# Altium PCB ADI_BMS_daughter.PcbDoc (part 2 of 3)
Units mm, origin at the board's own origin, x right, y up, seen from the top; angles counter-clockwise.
Board outline 140 x 50 mm, 4 copper layers (Top Layer, Layer 1, Layer 2, Bottom Layer), stack 1.586 mm thick; 306 components, 232 nets, 866 pads, 333 vias.
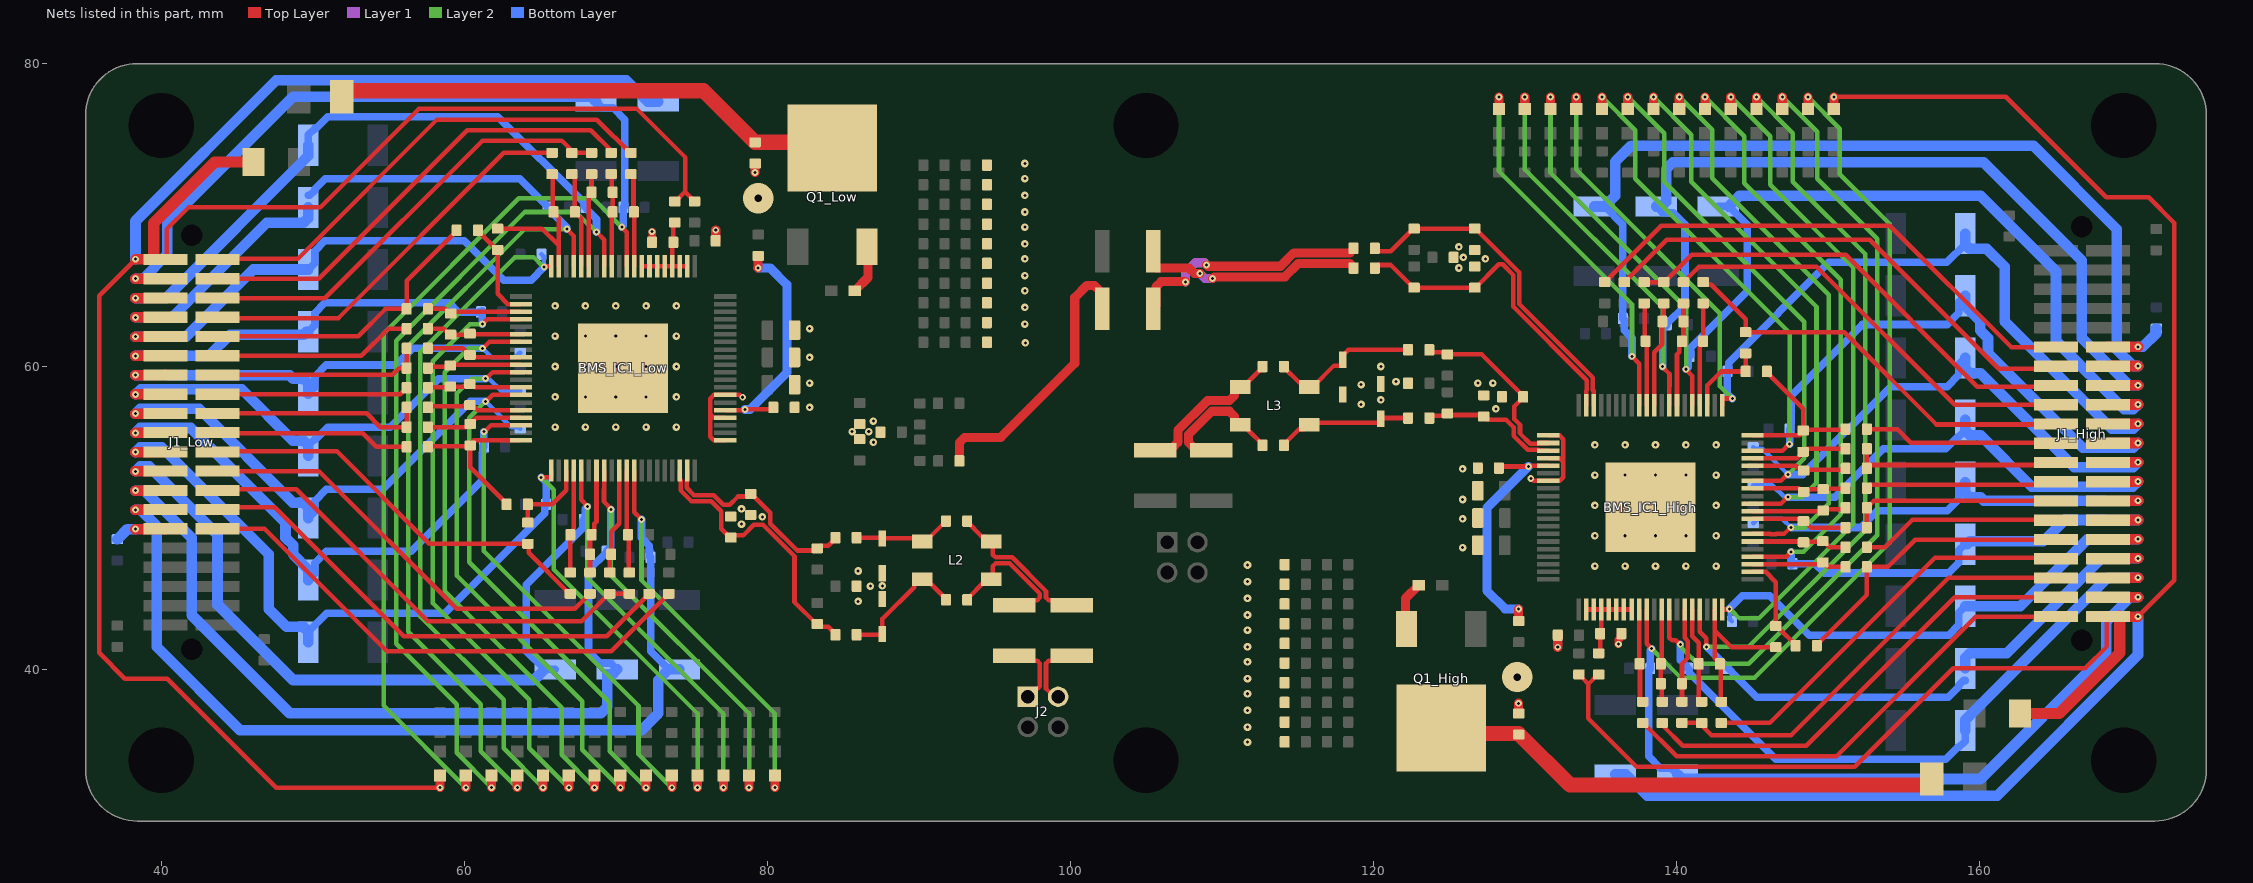
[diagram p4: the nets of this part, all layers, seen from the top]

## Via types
v1: diameter 0.45, hole 0.2, Top Layer to Bottom Layer, tented both sides, 226 vias
v2: diameter 0.5, hole 0.2, Top Layer to Bottom Layer, tented both sides, 105 vias
v3: diameter 2, hole 0.5, Top Layer to Bottom Layer, tented both sides, 2 vias

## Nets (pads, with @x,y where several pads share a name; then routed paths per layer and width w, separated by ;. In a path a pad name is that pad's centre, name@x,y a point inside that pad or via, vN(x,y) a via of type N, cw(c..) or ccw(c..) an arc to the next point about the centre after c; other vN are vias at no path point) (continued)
C2_High: BMS_IC1_High.51 C12_High.2 R15_High.2 | length 6.7
  Top Layer w0.3: R15_High.2@137.879,64.171 137.929,64.121 137.929,61.721 C12_High.2@137.979,61.671 ; BMS_IC1_High.51@138.05,57.438 C12_High.2@138.05,61.576
C2_Low: BMS_IC1_Low.51 C12_Low.2 R15_Low.2 | length 6.7
  Top Layer w0.3: C12_Low.2@70.729,48.995 BMS_IC1_Low.51@70.729,53.133 ; C12_Low.2@70.8,48.9 70.85,48.85 70.85,46.45 R15_Low.2@70.9,46.4
C3_High: BMS_IC1_High.50 C13_High.1 R16_High.2 | length 7
  Top Layer w0.3: BMS_IC1_High.50@138.55,57.438 138.55,60.943 139.079,61.471 C13_High.1@139.079,62.971 139.179,63.071 R16_High.2@139.179,64.171
C3_Low: BMS_IC1_Low.50 C13_Low.1 R16_Low.2 | length 7
  Top Layer w0.3: R16_Low.2@69.6,46.4 69.6,47.5 C13_Low.1@69.7,47.6 69.7,49.1 70.229,49.629 BMS_IC1_Low.50@70.229,53.133
C4:3_High: BMS_IC1_High.47 C13_High.2 C14_High.1 R17_High.2 | length 6.8
  Top Layer w0.3: BMS_IC1_High.47@140.05,57.438 140.05,60.803 140.199,60.952 140.199,61.441 C14_High.1@140.349,61.591 ; C14_High.1@140.379,61.671 140.479,61.771 R17_High.2@140.479,64.171
C4:3_Low: BMS_IC1_Low.47 C13_Low.2 C14_Low.1 R17_Low.2 | length 6.8
  Top Layer w0.3: R17_Low.2@68.3,46.4 68.3,48.8 C14_Low.1@68.4,48.9 ; C14_Low.1@68.43,48.98 68.58,49.13 68.58,49.62 68.729,49.768 BMS_IC1_Low.47@68.729,53.133
C4_High: BMS_IC1_High.44 C14_High.2 R18_High.2 | length 6.7
  Top Layer w0.3: BMS_IC1_High.44@141.55,57.438 141.55,61.293 C14_High.2@141.829,61.571 ; C14_High.2@141.779,61.671 R18_High.2@141.779,64.171
C4_Low: BMS_IC1_Low.44 C14_Low.2 R18_Low.2 | length 6.7
  Top Layer w0.3: C14_Low.2@66.95,49 67.229,49.278 BMS_IC1_Low.44@67.229,53.133 ; R18_Low.2@67,46.4 C14_Low.2@67,48.9
C5_High: BMS_IC1_High.43 C15_High.1 R19_High.2 | length 5.9
  Top Layer w0.3: BMS_IC1_High.43@142.05,57.438 142.05,58.75 142.971,59.671 C15_High.1@144.579,59.671 144.579,60.921 R19_High.2@144.629,60.971 ; R19_High.2@144.579,60.971 R19_High.2@144.629,60.971 ; R19_High.2@144.809,60.741 144.809,60.791 R19_High.2@144.629,60.971
C5_Low: BMS_IC1_Low.43 C15_Low.1 R19_Low.2 | length 5.9
  Top Layer w0.3: R19_Low.2@63.97,49.83 63.97,49.78 R19_Low.2@64.15,49.6 ; R19_Low.2@64.2,49.6 R19_Low.2@64.15,49.6 ; BMS_IC1_Low.43@66.729,53.133 66.729,51.821 65.807,50.9 C15_Low.1@64.2,50.9 64.2,49.65 R19_Low.2@64.15,49.6
C6:5_High: BMS_IC1_High.40 C15_High.2 C16_High.1 R20_High.2 | length 11.1
  Top Layer w0.3: BMS_IC1_High.40@145.038,55.45 148.15,55.45 C16_High.1@148.3,55.6 ; C15_High.2@145.979,59.671 145.979,59.622 148.379,57.222 C16_High.1@148.379,55.771 148.429,55.821 151.129,55.821 R20_High.2@151.179,55.871
C6:5_Low: BMS_IC1_Low.40 C15_Low.2 C16_Low.1 R20_Low.2 | length 11.1
  Top Layer w0.3: R20_Low.2@57.6,54.7 57.65,54.75 60.35,54.75 C16_Low.1@60.4,54.8 60.4,53.35 62.8,50.95 C15_Low.2@62.8,50.9 ; C16_Low.1@60.479,54.971 60.629,55.121 BMS_IC1_Low.40@63.741,55.121
C6_High: BMS_IC1_High.37 C16_High.2 R21_High.2 | length 6.4
  Top Layer w0.3: BMS_IC1_High.37@145.038,53.95 147.973,53.95 148.149,54.126 148.149,54.191 148.354,54.396 148.453,54.396 148.629,54.571 R21_High.2@151.179,54.571
C6_Low: BMS_IC1_Low.37 C16_Low.2 R21_Low.2 | length 6.4
  Top Layer w0.3: R21_Low.2@57.6,56 60.15,56 60.325,56.175 60.425,56.175 60.63,56.38 60.63,56.446 60.806,56.621 BMS_IC1_Low.37@63.741,56.621
C7_High: BMS_IC1_High.36 C17_High.1 R22_High.2 | length 6.3
  Top Layer w0.3: BMS_IC1_High.36@145.038,53.45 147.9,53.45 C17_High.1@148.25,53.1 ; C17_High.1@148.3,53.1 C17_High.1@148.35,53.15 ; C17_High.1@148.404,53.121 148.479,53.196 151.104,53.196 R22_High.2@151.179,53.271
C7_Low: BMS_IC1_Low.36 C17_Low.1 R22_Low.2 | length 6.3
  Top Layer w0.3: R22_Low.2@57.6,57.3 57.675,57.375 60.3,57.375 C17_Low.1@60.375,57.45 ; C17_Low.1@60.429,57.421 C17_Low.1@60.479,57.471 ; C17_Low.1@60.529,57.471 60.879,57.121 BMS_IC1_Low.36@63.741,57.121
C8:7_High: BMS_IC1_High.33 C17_High.2 C18_High.1 R23_High.2 | length 6.4
  Top Layer w0.3: BMS_IC1_High.33@145.038,51.95 148.1,51.95 148.3,51.75 148.3,51.7 148.4,51.7 148.6,51.9 C18_High.1@149.7,51.9 149.736,51.936 151.143,51.936 R23_High.2@151.179,51.971
C8:7_Low: BMS_IC1_Low.33 C17_Low.2 C18_Low.1 R23_Low.2 | length 6.4
  Top Layer w0.3: R23_Low.2@57.6,58.6 57.636,58.636 59.043,58.636 C18_Low.1@59.079,58.671 60.179,58.671 60.379,58.871 60.479,58.871 60.479,58.821 60.679,58.621 BMS_IC1_Low.33@63.741,58.621
C8_High: BMS_IC1_High.30 C18_High.2 R24_High.2 | length 6.1
  Top Layer w0.3: BMS_IC1_High.30@145.038,50.45 C18_High.2@149.55,50.45 ; C18_High.2@149.7,50.5 149.786,50.586 151.093,50.586 R24_High.2@151.179,50.671
C8_Low: BMS_IC1_Low.30 C18_Low.2 R24_Low.2 | length 6.1
  Top Layer w0.3: R24_Low.2@57.6,59.9 57.686,59.986 58.993,59.986 C18_Low.2@59.079,60.071 ; C18_Low.2@59.229,60.121 BMS_IC1_Low.30@63.741,60.121
C9_High: BMS_IC1_High.29 C19_High.1 R25_High.2 | length 6.2
  Top Layer w0.3: BMS_IC1_High.29@145.038,49.95 C19_High.1@148.3,49.95 ; C19_High.1@148.4,49.8 148.45,49.8 148.878,49.371 R25_High.2@151.179,49.371
C9_Low: BMS_IC1_Low.29 C19_Low.1 R25_Low.2 | length 6.2
  Top Layer w0.3: R25_Low.2@57.6,61.2 59.9,61.2 60.329,60.771 C19_Low.1@60.379,60.771 ; C19_Low.1@60.479,60.621 BMS_IC1_Low.29@63.741,60.621
C10:9_High: BMS_IC1_High.26 C19_High.2 C20_High.1 R26_High.2 | length 6.4
  Top Layer w0.3: BMS_IC1_High.26@145.038,48.45 148.25,48.45 C19_High.2@148.4,48.3 ; C19_High.2@148.4,48.4 148.436,48.436 149.693,48.436 149.729,48.471 150.129,48.071 R26_High.2@151.179,48.071
C10:9_Low: BMS_IC1_Low.26 C19_Low.2 C20_Low.1 R26_Low.2 | length 6.4
  Top Layer w0.3: R26_Low.2@57.6,62.5 58.65,62.5 59.05,62.1 60.307,62.1 C19_Low.2@60.379,62.171 ; C19_Low.2@60.379,62.271 60.529,62.121 BMS_IC1_Low.26@63.741,62.121
C10_High: BMS_IC1_High.23 C20_High.2 R27_High.2 | length 6.3
  Top Layer w0.3: BMS_IC1_High.23@145.038,46.95 C20_High.2@149.679,46.95 ; C20_High.2@149.679,47.071 149.729,47.071 150.029,46.771 R27_High.2@151.179,46.771
C10_Low: BMS_IC1_Low.23 C20_Low.2 R27_Low.2 | length 6.3
  Top Layer w0.3: R27_Low.2@57.6,63.8 58.75,63.8 59.05,63.5 C20_Low.2@59.1,63.5 ; C20_Low.2@59.1,63.621 BMS_IC1_Low.23@63.741,63.621
C11_High: BMS_IC1_High.22 C21_High.1 R28_High.2 | length 6.6
  Top Layer w0.3: BMS_IC1_High.22@145.038,46.45 145.9,46.45 146.579,45.771 C21_High.1@146.579,42.871 146.629,42.871 146.809,42.691 147.879,41.621 R28_High.2@147.879,41.571
C11_Low: BMS_IC1_Low.22 C21_Low.1 R28_Low.2 | length 6.6
  Top Layer w0.3: R28_Low.2@60.9,69 60.9,68.95 61.97,67.88 62.15,67.7 C21_Low.1@62.2,67.7 62.2,64.8 62.879,64.121 BMS_IC1_Low.22@63.741,64.121
C12:11_High: BMS_IC1_High.19 C21_High.2 C22_High.1 R29_High.2 | length 10.8
  Top Layer w0.3: BMS_IC1_High.19@142.55,43.962 142.55,42.571 ; R29_High.2@142.979,37.871 142.929,37.921 142.929,40.321 C22_High.1@142.879,40.371 142.879,40.421 142.55,40.75 142.55,42.571 ; C21_High.2@146.579,41.471 143.65,41.471 142.55,42.571
C12:11_Low: BMS_IC1_Low.19 C21_Low.2 C22_Low.1 R29_Low.2 | length 10.8
  Top Layer w0.3: C21_Low.2@62.2,69.1 65.129,69.1 66.229,68 ; R29_Low.2@65.8,72.7 65.85,72.65 65.85,70.25 C22_Low.1@65.9,70.2 65.9,70.15 66.229,69.822 66.229,68 ; BMS_IC1_Low.19@66.229,66.609 66.229,68
C12_High: BMS_IC1_High.16 C22_High.2 R30_High.2 | length 6.4
  Top Layer w0.3: BMS_IC1_High.16@141.05,43.962 141.05,42.202 141.479,41.774 141.479,38.051 141.659,37.871 R30_High.2@141.679,37.871
C12_Low: BMS_IC1_Low.16 C22_Low.2 R30_Low.2 | length 6.4
  Top Layer w0.3: R30_Low.2@67.1,72.7 67.12,72.7 67.3,72.52 C22_Low.2@67.3,70.15 ; C22_Low.2@67.3,70.2 C22_Low.2@67.3,70.15 ; BMS_IC1_Low.16@67.729,66.609 67.729,69.771 67.53,69.97 67.48,69.97 C22_Low.2@67.3,70.15
C13_High: BMS_IC1_High.15 C23_High.1 R31_High.2 | length 6.3
  Top Layer w0.3: R31_High.2@140.379,37.871 C23_High.1@140.379,39.071 140.379,40.389 140.772,40.783 140.772,41.871 140.55,42.093 BMS_IC1_High.15@140.55,43.962
C13_Low: BMS_IC1_Low.15 C23_Low.1 R31_Low.2 | length 6.2
  Top Layer w0.3: BMS_IC1_Low.15@68.229,66.609 68.229,71.329 C23_Low.1@68.4,71.5 R31_Low.2@68.4,72.7
C14:13_High: BMS_IC1_High.12 C23_High.2 C24_High.1 R32_High.2 | length 6.2
  Top Layer w0.3: BMS_IC1_High.12@139.05,43.962 139.05,40.443 C24_High.1@138.979,40.371 C23_High.2@138.979,39.071 139.029,39.021 139.029,37.921 R32_High.2@139.079,37.871
C14:13_Low: BMS_IC1_Low.12 C23_Low.2 C24_Low.1 R32_Low.2 | length 6.2
  Top Layer w0.3: R32_Low.2@69.7,72.7 69.75,72.65 69.75,71.55 C23_Low.2@69.8,71.5 C24_Low.1@69.8,70.2 69.729,70.129 BMS_IC1_Low.12@69.729,66.609
C14_High: BMS_IC1_High.9 C24_High.2 R33_High.2 | length 6.2
  Top Layer w0.3: C24_High.2@137.55,40.371 BMS_IC1_High.9@137.55,43.962 ; C24_High.2@137.579,40.371 137.607,40.343 137.607,38.043 R33_High.2@137.779,37.871
C14_Low: BMS_IC1_Low.9 C24_Low.2 R33_Low.2 | length 6.2
  Top Layer w0.3: R33_Low.2@71,72.7 71.171,72.529 71.171,70.229 C24_Low.2@71.2,70.2 ; BMS_IC1_Low.9@71.229,66.609 C24_Low.2@71.229,70.2
CEll0_High: J1_High.30 R13_High.1 | length 34.6
  Top Layer w0.3: R13_High.1@135.279,65.571 139.007,69.3 154.097,69.3 162.11,61.286 J1_High.30@165.064,61.286
CEll0_Low: J1_Low.30 R13_Low.1 | length 34.7
  Top Layer w0.3: J1_Low.30@43.715,49.285 46.815,49.285 52.9,43.2 54.9,41.2 69.7,41.2 R13_Low.1@73.5,45
Cell1_High: J1_High.28 R14_High.1 | length 33
  Top Layer w0.3: R14_High.1@136.579,65.571 139.379,68.371 152.779,68.371 161.292,59.858 164.697,59.858 J1_High.28@164.81,59.971
Cell1_Low: J1_Low.28 R14_Low.1 | length 33
  Top Layer w0.3: J1_Low.28@43.968,50.6 44.081,50.713 47.487,50.713 56,42.2 69.4,42.2 R14_Low.1@72.2,45
Cell1_S_High: BMS_IC1_High.52 C26_High.1 D1_High.2 J1_High.27 R35_High.1 | length 87.1
  Top Layer w0.3: v1(137.079,60.671) 137.079,60.667 137.554,60.192 137.554,59.179 137.55,59.175 BMS_IC1_High.52@137.55,57.438
  Top Layer w0.6: D1_High.2@128.3,77 v1(128.3,77.8)
  Top Layer w0.7: J1_High.27@168.494,60.016 168.509,60.031 v1(170.479,60.031)
  Layer 2 w0.3: v1(128.3,77.8) 128.3,72.9 137.079,64.121 v1(137.079,60.671)
  Bottom Layer w0.5: R35_High.1@135.274,70.565 136.479,69.36 C26_High.1@136.479,63.171 136.559,63.091 136.559,62.391 137.079,61.871 v1(137.079,60.671)
  Bottom Layer w0.7: R35_High.1@134.579,70.565 135.274,70.565 135.979,71.27 135.979,73.529 136.969,74.519 ; 137.079,74.571 163.579,74.571 169.079,69.071 169.079,61.102 170.15,60.031 v1(170.479,60.031)
Cell1_S_Low: BMS_IC1_Low.52 C26_Low.1 D1_Low.2 J1_Low.27 R35_Low.1 | length 87.7
  Top Layer w0.3: BMS_IC1_Low.52@71.229,53.133 71.229,51.396 71.225,51.392 71.225,50.379 71.7,49.904 v1(71.7,49.9)
  Top Layer w0.6: v1(80.5,32.2) D1_Low.2@80.5,33
  Top Layer w0.7: v1(38.3,50.54) 40.27,50.54 J1_Low.27@40.285,50.555
  Layer 2 w0.3: v1(71.7,49.9) 71.7,45.9 80.5,37.1 v1(80.5,32.2)
  Bottom Layer w0.5: v1(71.7,49.9) 71.7,48.7 72.22,48.18 72.22,47.48 C26_Low.1@72.3,47.4 72.3,41.211 R35_Low.1@73.505,40.006
  Bottom Layer w0.7: v1(38.3,50.54) 38.629,50.54 39.7,49.469 39.7,41.5 45.2,36 71.7,36 72.8,37.1 72.8,39.301 73.505,40.006 R35_Low.1@74.2,40.006
Cell2_High: J1_High.26 R15_High.1 R16_High.1 | length 31.2
  Top Layer w0.3: R15_High.1@137.879,65.571 R16_High.1@139.179,65.571 ; R16_High.1@139.22,65.571 139.229,65.571 139.409,65.752 139.409,65.76 141.02,67.371 151.179,67.371 159.879,58.671 J1_High.26@164.775,58.671
Cell2_Low: J1_Low.26 R15_Low.1 R16_Low.1 | length 31.2
  Top Layer w0.3: J1_Low.26@44.004,51.9 48.9,51.9 57.6,43.2 67.75,43.2 69.525,44.975 R16_Low.1@69.575,44.975 ; R16_Low.1@69.6,45 R15_Low.1@70.9,45
Cell2_S_High: BMS_IC1_High.48 C27_High.1 D2_High.2 J1_High.25 R36_High.1 | length 82.9
  Top Layer w0.3: v1(139.1,60) 139.1,59.959 139.554,59.505 139.554,58.688 139.55,58.684 BMS_IC1_High.48@139.55,57.445
  Top Layer w0.6: D2_High.2@130,76.9 D2_High.2@130,77 v1(130,77.8)
  Top Layer w0.7: J1_High.25@168.494,58.746 168.509,58.761 v1(170.479,58.761)
  Layer 2 w0.3: v1(130,77.8) 130,73 139.1,63.9 v1(139.1,60)
  Bottom Layer w0.5: R36_High.1@138.679,70.565 139.094,70.15 139.8,70.15 140.579,69.371 140.579,64.021 139.379,62.821 C27_High.1@139.379,62.771 ; v1(139.1,60) 139.1,62.443 C27_High.1@139.379,62.721
  Bottom Layer w0.7: R36_High.1@138.679,70.565 139.013,70.565 139.328,70.88 139.328,73.028 139.771,73.471 160.279,73.471 166.779,66.971 166.779,61.871 169.889,58.761 v1(170.479,58.761)
Cell2_S_Low: BMS_IC1_Low.48 C27_Low.1 D2_Low.2 J1_Low.25 R36_Low.1 | length 83.5
  Top Layer w0.3: BMS_IC1_Low.48@69.229,53.127 69.229,51.887 69.225,51.883 69.225,51.066 69.679,50.612 v1(69.679,50.571)
  Top Layer w0.6: v1(78.8,32.2) D2_Low.2@78.8,33 D2_Low.2@78.8,33.1
  Top Layer w0.7: v1(38.3,51.81) 40.27,51.81 J1_Low.25@40.285,51.825
  Layer 2 w0.3: v1(69.679,50.571) 69.679,46.221 78.8,37.1 v1(78.8,32.2)
  Bottom Layer w0.5: C27_Low.1@69.4,47.8 69.4,47.75 68.2,46.55 68.2,41.2 68.979,40.421 69.685,40.421 R36_Low.1@70.1,40.006 ; C27_Low.1@69.4,47.85 69.679,48.129 v1(69.679,50.571)
  Bottom Layer w0.7: v1(38.3,51.81) 38.89,51.81 42,48.7 42,43.6 48.5,37.1 69,37.1 69.451,37.551 69.451,39.691 69.785,39.691 R36_Low.1@70.1,40.006
Cell3_High: J1_High.24 R17_High.1 | length 28.9
  Top Layer w0.3: R17_High.1@140.479,65.571 140.528,65.571 140.709,65.752 140.709,65.801 141.479,66.571 149.279,66.571 158.379,57.471 J1_High.24@165.141,57.471
Cell3_Low: J1_Low.24 R17_Low.1 | length 28.9
  Top Layer w0.3: J1_Low.24@43.638,53.1 50.4,53.1 59.5,44 67.3,44 68.07,44.77 68.07,44.82 68.25,45 R17_Low.1@68.3,45
Cell3_S_High: BMS_IC1_High.45 C28_High.1 D3_High.2 J1_High.23 R37_High.1 | length 76.6
  Top Layer w0.3: v1(140.65,59.819) 140.65,59.778 141.054,59.374 141.054,58.563 141.05,58.559 BMS_IC1_High.45@141.05,57.438
  Top Layer w0.6: D3_High.2@131.7,77 v1(131.7,77.8)
  Top Layer w0.7: J1_High.23@168.494,57.476 168.509,57.491 v1(170.479,57.491)
  Layer 2 w0.3: v1(131.7,77.8) 131.7,72.8 140.65,63.85 v1(140.65,59.819)
  Bottom Layer w0.5: v1(140.65,59.819) 140.798,59.967 140.798,60.647 C28_High.1@140.822,60.671 ; C28_High.1@140.879,60.671 140.959,60.752 140.959,61.251 144.679,64.971 144.679,69.36 143.474,70.565 R37_High.1@142.779,70.565
  Bottom Layer w0.7: R37_High.1@143.474,70.565 144.174,71.265 160.085,71.265 165.066,66.284 165.066,61.684 169.578,57.172 170.16,57.172 v1(170.479,57.491)
Cell3_S_Low: BMS_IC1_Low.45 C28_Low.1 D3_Low.2 J1_Low.23 R37_Low.1 | length 77.2
  Top Layer w0.3: BMS_IC1_Low.45@67.729,53.133 67.729,52.012 67.725,52.008 67.725,51.197 68.129,50.793 v1(68.129,50.753)
  Top Layer w0.6: v1(77.1,32.2) D3_Low.2@77.1,33
  Top Layer w0.7: v1(38.3,53.08) 40.27,53.08 J1_Low.23@40.285,53.095
  Layer 2 w0.3: v1(68.129,50.753) 68.129,46.071 77.1,37.1 v1(77.1,32.2)
  Bottom Layer w0.5: R37_Low.1@66,40.006 65.305,40.006 64.1,41.211 64.1,45.6 67.82,49.32 67.82,49.82 C28_Low.1@67.9,49.9 ; C28_Low.1@67.956,49.9 67.98,49.924 67.98,50.604 v1(68.129,50.753)
  Bottom Layer w0.7: v1(38.3,53.08) 38.619,53.399 39.201,53.399 43.713,48.887 43.713,44.287 48.694,39.306 64.605,39.306 R37_Low.1@65.305,40.006
Cell4_High: J1_High.22 R18_High.1 R19_High.1 | length 27.8
  Top Layer w0.3: R18_High.1@141.779,65.571 141.959,65.391 142.309,65.391 144.579,63.121 R19_High.1@144.579,62.271 151.079,62.271 157.179,56.171 J1_High.22@165.216,56.171
Cell4_Low: J1_Low.22 R18_Low.1 R19_Low.1 | length 27.7
  Top Layer w0.3: J1_Low.22@43.563,54.4 51.6,54.4 57.7,48.3 R19_Low.1@64.2,48.3 64.255,48.245 64.255,47.696 66.95,45 R18_Low.1@67,45
Cell4_S_High: BMS_IC1_High.41 C29_High.1 D4_High.2 J1_High.21 R38_High.1 | length 69
  Top Layer w0.3: BMS_IC1_High.41@143.05,57.438 BMS_IC1_High.41@143.05,57.888 ; BMS_IC1_High.41@143.05,57.9 BMS_IC1_High.41@143.05,57.888 ; v1(143.7,57.888) BMS_IC1_High.41@143.05,57.888
  Top Layer w0.6: D4_High.2@133.4,76.9 v1(133.4,77.8)
  Top Layer w0.7: J1_High.21@168.494,56.206 168.509,56.221 v1(170.479,56.221)
  Layer 2 w0.3: v1(133.4,77.8) 133.4,73 142.879,63.521 142.879,58.709 v1(143.7,57.888)
  Bottom Layer w0.5: v1(143.7,57.888) 143.379,58.209 C29_High.1@143.379,59.671 143.459,59.752 143.459,60.251 150.079,66.871 157.868,66.871 R38_High.1@159.073,68.076
  Bottom Layer w0.7: R38_High.1@159.073,68.771 159.073,68.076 159.388,67.761 160.489,67.761 161.675,66.575 161.675,62.968 168.74,55.902 170.16,55.902 v1(170.479,56.221)
Cell4_S_Low: BMS_IC1_Low.41 C29_Low.1 D4_Low.2 J1_Low.21 R38_Low.1 | length 69.5
  Top Layer w0.3: v1(65.079,52.683) BMS_IC1_Low.41@65.729,52.683 ; BMS_IC1_Low.41@65.729,52.671 BMS_IC1_Low.41@65.729,52.683 ; BMS_IC1_Low.41@65.729,53.133 BMS_IC1_Low.41@65.729,52.683
  Top Layer w0.6: v1(75.4,32.2) D4_Low.2@75.4,33.1
  Top Layer w0.7: v1(38.3,54.35) 40.27,54.35 J1_Low.21@40.285,54.365
  Layer 2 w0.3: v1(65.079,52.683) 65.9,51.862 65.9,46.6 75.4,37.1 v1(75.4,32.2)
  Bottom Layer w0.5: R38_Low.1@49.706,42.495 50.911,43.7 58.7,43.7 65.32,50.32 65.32,50.82 C29_Low.1@65.4,50.9 65.4,52.362 v1(65.079,52.683)
  Bottom Layer w0.7: v1(38.3,54.35) 38.619,54.669 40.038,54.669 47.104,47.603 47.104,43.996 48.29,42.81 49.391,42.81 49.706,42.495 R38_Low.1@49.706,41.8
Cell5_High: J1_High.20 R20_High.1 | length 12.9
  Top Layer w0.3: R20_High.1@152.579,55.871 154.579,55.871 155.479,54.971 J1_High.20@165.138,54.971
Cell5_Low: J1_Low.20 R20_Low.1 | length 12.9
  Top Layer w0.3: J1_Low.20@43.641,55.6 53.3,55.6 54.2,54.7 R20_Low.1@56.2,54.7
Cell5_S_High: BMS_IC1_High.38 C30_High.1 D5_High.2 J1_High.19 R39_High.1 | length 68.5
  Top Layer w0.3: BMS_IC1_High.38@145.038,54.45 146.117,54.45 146.121,54.446 147.011,54.446 147.438,54.873 v1(147.479,54.873)
  Top Layer w0.6: D5_High.2@135.1,77 v1(135.1,77.8)
  Top Layer w0.7: J1_High.19@168.494,54.936 168.509,54.951 v1(170.479,54.951)
  Layer 2 w0.3: v1(135.1,77.8) 137.3,75.6 137.3,72.4 147.479,62.221 v1(147.479,54.873)
  Bottom Layer w0.5: v1(147.479,54.873) C30_High.1@147.479,55.871 ; C30_High.1@147.499,55.791 147.559,55.852 147.559,56.26 147.579,56.28 147.579,58.071 152.279,62.771 157.879,62.771 158.658,63.55 158.658,64.256 R39_High.1@159.073,64.671
  Bottom Layer w0.7: R39_High.1@159.073,64.671 159.073,63.976 160.073,62.976 160.073,62.381 160.579,61.875 160.579,60.877 166.823,54.632 170.16,54.632 v1(170.479,54.951)
Cell5_S_Low: BMS_IC1_Low.38 C30_Low.1 D5_Low.2 J1_Low.19 R39_Low.1 | length 69
  Top Layer w0.3: v1(61.3,55.698) 61.341,55.698 61.768,56.125 62.658,56.125 62.662,56.121 BMS_IC1_Low.38@63.741,56.121
  Top Layer w0.6: v1(73.7,32.2) D5_Low.2@73.7,33
  Top Layer w0.7: v1(38.3,55.62) 40.27,55.62 J1_Low.19@40.285,55.635
  Layer 2 w0.3: v1(61.3,55.698) 61.3,47.8 71.5,37.6 71.5,34.4 v1(73.7,32.2)
  Bottom Layer w0.5: R39_Low.1@49.706,45.9 50.121,46.315 50.121,47.021 50.9,47.8 56.5,47.8 61.2,52.5 61.2,54.292 61.22,54.311 61.22,54.72 C30_Low.1@61.28,54.78 ; C30_Low.1@61.3,54.7 v1(61.3,55.698)
  Bottom Layer w0.7: v1(38.3,55.62) 38.619,55.939 41.956,55.939 48.2,49.695 48.2,48.696 48.706,48.191 48.706,47.595 49.706,46.595 R39_Low.1@49.706,45.9
Cell6_High: J1_High.18 R21_High.1 R22_High.1 | length 14
  Top Layer w0.3: R21_High.1@152.579,54.571 R22_High.1@152.579,53.271 152.579,53.32 152.759,53.5 164.897,53.5 J1_High.18@165.064,53.666
Cell6_Low: J1_Low.18 R21_Low.1 R22_Low.1 | length 14.2
  Top Layer w0.3: J1_Low.18@43.715,56.905 53.557,56.905 54.462,56 R21_Low.1@56.2,56 R22_Low.1@56.2,57.3
Cell6_S_High: BMS_IC1_High.34 C31_High.1 D6_High.2 J1_High.17 R40_High.1 | length 68.9
  Top Layer w0.3: BMS_IC1_High.34@145.038,52.45 146.088,52.45 146.092,52.446 146.909,52.446 147.336,52.873 v1(147.377,52.873)
  Top Layer w0.6: D6_High.2@136.8,76.9 v1(136.8,77.8)
  Top Layer w0.7: J1_High.17@168.494,53.666 168.509,53.681 v1(170.479,53.681)
  Layer 2 w0.3: v1(136.8,77.8) 139.2,75.4 139.2,72.2 148.456,62.944 148.456,53.953 v1(147.377,52.873)
  Bottom Layer w0.3: C31_High.1@145.079,54.671 145.178,54.572 145.678,54.572 v1(147.377,52.873)
  Bottom Layer w0.5: v1(147.377,52.873) 148.364,52.873 154.162,58.671 157.879,58.671 158.658,59.45 158.658,60.156 R40_High.1@159.073,60.571
  Bottom Layer w0.7: R40_High.1@159.073,60.571 159.073,59.876 159.388,59.561 160.083,59.561 166.282,53.362 170.16,53.362 v1(170.479,53.681)
Cell6_S_Low: BMS_IC1_Low.34 C31_Low.1 D6_Low.2 J1_Low.17 R40_Low.1 | length 69.5
  Top Layer w0.3: v1(61.402,57.698) 61.443,57.698 61.87,58.125 62.687,58.125 62.691,58.121 BMS_IC1_Low.34@63.741,58.121
  Top Layer w0.6: v1(72,32.2) D6_Low.2@72,33.1
  Top Layer w0.7: v1(38.3,56.89) 40.27,56.89 J1_Low.17@40.285,56.905
  Layer 2 w0.3: v1(61.402,57.698) 60.322,56.618 60.322,47.078 69.6,37.8 69.6,34.6 v1(72,32.2)
  Bottom Layer w0.3: v1(61.402,57.698) 63.101,55.999 63.601,55.999 C31_Low.1@63.7,55.9
  Bottom Layer w0.5: R40_Low.1@49.706,50 50.121,50.415 50.121,51.121 50.9,51.9 54.616,51.9 60.414,57.698 v1(61.402,57.698)
  Bottom Layer w0.7: v1(38.3,56.89) 38.619,57.209 42.497,57.209 48.696,51.01 49.391,51.01 49.706,50.695 R40_Low.1@49.706,50
Cell7_High: J1_High.16 R23_High.1 | length 12.7
  Top Layer w0.3: R23_High.1@152.579,51.971 152.579,52.02 152.759,52.2 164.867,52.2 J1_High.16@165.064,52.396
Cell7_Low: J1_Low.16 R23_Low.1 | length 12.7
  Top Layer w0.3: J1_Low.16@43.715,58.175 55.775,58.175 55.97,58.37 56.02,58.37 56.2,58.55 R23_Low.1@56.2,58.6
Cell7_S_High: BMS_IC1_High.31 C32_High.1 D7_High.2 J1_High.15 R41_High.1 | length 67.4
  Top Layer w0.3: BMS_IC1_High.31@144.538,50.95 BMS_IC1_High.31@144.542,50.946 ; BMS_IC1_High.31@145.038,50.95 146.088,50.95 146.092,50.946 146.913,50.946 147.338,51.371 v1(147.379,51.371)
  Top Layer w0.6: D7_High.2@138.5,77 v1(138.5,77.8)
  Top Layer w0.7: J1_High.15@168.494,52.396 168.509,52.411 v1(170.479,52.411)
  Layer 2 w0.3: v1(138.5,77.8) 141,75.3 141,72.2 149.259,63.94 149.259,52.327 148.304,51.371 v1(147.379,51.371)
  Bottom Layer w0.3: C32_High.1@145.079,52.171 146.348,52.171 147.119,51.4 147.35,51.4 v1(147.379,51.371)
  Bottom Layer w0.5: v1(147.379,51.371) 150.479,51.371 153.679,54.571 157.779,54.571 158.569,55.361 158.658,55.361 R41_High.1@159.073,55.776
  Bottom Layer w0.7: R41_High.1@159.073,56.471 159.073,55.776 159.388,55.461 160.083,55.461 163.473,52.071 170.139,52.071 v1(170.479,52.411)
Cell7_S_Low: BMS_IC1_Low.31 C32_Low.1 D7_Low.2 J1_Low.15 R41_Low.1 | length 68
  Top Layer w0.3: v1(61.4,59.2) 61.441,59.2 61.866,59.625 62.687,59.625 62.691,59.621 BMS_IC1_Low.31@63.741,59.621 ; BMS_IC1_Low.31@64.237,59.625 BMS_IC1_Low.31@64.241,59.621
  Top Layer w0.6: v1(70.3,32.2) D7_Low.2@70.3,33
  Top Layer w0.7: v1(38.3,58.16) 40.27,58.16 J1_Low.15@40.285,58.175
  Layer 2 w0.3: v1(61.4,59.2) 60.475,59.2 59.519,58.244 59.519,46.181 67.8,37.9 67.8,34.7 v1(70.3,32.2)
  Bottom Layer w0.3: v1(61.4,59.2) 61.429,59.171 61.66,59.171 62.431,58.4 C32_Low.1@63.7,58.4
  Bottom Layer w0.5: R41_Low.1@49.706,54.795 50.121,55.21 50.21,55.21 51,56 55.1,56 58.3,59.2 v1(61.4,59.2)
  Bottom Layer w0.7: v1(38.3,58.16) 38.64,58.5 45.306,58.5 48.696,55.11 49.391,55.11 49.706,54.795 R41_Low.1@49.706,54.1
Cell8_High: J1_High.14 R24_High.1 R25_High.1 | length 14
  Top Layer w0.3: R25_High.1@152.579,49.371 R24_High.1@152.579,50.671 ; R24_High.1@152.579,50.721 152.759,50.901 152.809,50.901 153.034,51.126 J1_High.14@165.064,51.126
Cell8_Low: J1_Low.14 R24_Low.1 R25_Low.1 | length 14.2
  Top Layer w0.3: J1_Low.14@43.715,59.445 55.245,59.445 55.7,59.9 R24_Low.1@56.15,59.9 ; R25_Low.1@56.02,60.97 R25_Low.1@56.2,61.15 ; R24_Low.1@56.2,59.9 R25_Low.1@56.2,61.2
Cell8_S_High: BMS_IC1_High.27 C33_High.1 D8_High.2 J1_High.13 R49_High.1 | length 68
  Top Layer w0.3: BMS_IC1_High.27@145.038,48.95 146.188,48.95 146.195,48.943 146.611,48.943 146.615,48.946 147.113,48.946 147.538,49.371 v1(147.579,49.371)
  Top Layer w0.6: D8_High.2@140.2,76.9 v1(140.2,77.8)
  Top Layer w0.7: J1_High.13@168.494,51.126 168.509,51.141 v1(170.479,51.141)
  Layer 2 w0.3: v1(140.2,77.8) 142.375,75.625 142.375,72.425 150.063,64.737 150.063,50.955 148.479,49.371 v1(147.579,49.371)
  Bottom Layer w0.3: C33_High.1@145.079,49.671 145.128,49.671 145.404,49.947 147.003,49.947 v1(147.579,49.371)
  Bottom Layer w0.5: v1(147.579,49.371) 152.179,49.371 153.279,50.471 157.879,50.471 158.658,51.25 158.658,51.956 R49_High.1@159.073,52.371
  Bottom Layer w0.7: R49_High.1@159.073,52.371 159.073,51.676 159.388,51.361 160.083,51.361 160.303,51.141 v1(170.479,51.141)
Cell8_S_Low: BMS_IC1_Low.27 C33_Low.1 D8_Low.2 J1_Low.13 R49_Low.1 | length 68.6
  Top Layer w0.3: v1(61.2,61.2) 61.241,61.2 61.666,61.625 62.164,61.625 62.167,61.629 62.583,61.629 62.591,61.621 BMS_IC1_Low.27@63.741,61.621
  Top Layer w0.6: v1(68.6,32.2) D8_Low.2@68.6,33.1
  Top Layer w0.7: v1(38.3,59.43) 40.27,59.43 J1_Low.13@40.285,59.445
  Layer 2 w0.3: v1(61.2,61.2) 60.3,61.2 58.716,59.616 58.716,45.184 66.425,37.475 66.425,34.375 v1(68.6,32.2)
  Bottom Layer w0.3: v1(61.2,61.2) 61.775,60.625 63.375,60.625 63.65,60.9 C33_Low.1@63.7,60.9
  Bottom Layer w0.5: R49_Low.1@49.706,58.2 50.121,58.615 50.121,59.321 50.9,60.1 55.5,60.1 56.6,61.2 v1(61.2,61.2)
  Bottom Layer w0.7: v1(38.3,59.43) 48.476,59.43 48.696,59.21 49.391,59.21 49.706,58.895 R49_Low.1@49.706,58.2
Cell9_High: J1_High.12 R26_High.1 | length 13.3
  Top Layer w0.3: R26_High.1@152.579,48.071 153.779,48.071 155.579,49.871 J1_High.12@165.142,49.871
Cell9_Low: J1_Low.12 R26_Low.1 | length 13.3
  Top Layer w0.3: J1_Low.12@43.637,60.7 53.2,60.7 55,62.5 R26_Low.1@56.2,62.5
Cell9_S_High: BMS_IC1_High.24 C34_High.1 D9_High.2 J1_High.11 R50_High.1 | length 66.9
  Top Layer w0.3: BMS_IC1_High.24@145.038,47.45 146.088,47.45 146.092,47.446 147.253,47.446 v1(147.579,47.771)
  Top Layer w0.6: D9_High.2@141.9,77 v1(141.9,77.8)
  Top Layer w0.7: J1_High.11@168.494,49.856 168.509,49.871 v1(170.479,49.871)
  Layer 2 w0.3: v1(141.9,77.8) 144.5,75.2 144.5,72.1 150.866,65.734 150.866,50.234 148.404,47.771 v1(147.579,47.771)
  Bottom Layer w0.5: v1(147.579,47.771) 147.598,47.751 147.598,47.052 C34_High.1@147.679,46.971 C34_High.1@147.598,46.891 ; C34_High.1@147.779,46.971 147.798,46.991 149.159,46.991 149.779,46.371 157.979,46.371 158.658,47.05 158.658,47.856 R50_High.1@159.073,48.271
  Bottom Layer w0.7: R50_High.1@159.073,48.271 159.189,48.271 159.388,48.47 164.233,48.47 165.634,49.871 v1(170.479,49.871)
Cell9_S_Low: BMS_IC1_Low.24 C34_Low.1 D9_Low.2 J1_Low.11 R50_Low.1 | length 67.5
  Top Layer w0.3: v1(61.2,62.8) 61.525,63.125 62.687,63.125 62.691,63.121 BMS_IC1_Low.24@63.741,63.121
  Top Layer w0.6: v1(66.9,32.2) D9_Low.2@66.9,33
  Top Layer w0.7: v1(38.3,60.7) 40.27,60.7 J1_Low.11@40.285,60.715
  Layer 2 w0.3: v1(61.2,62.8) 60.375,62.8 57.913,60.338 57.913,44.387 64.3,38 64.3,34.8 v1(66.9,32.2)
  Bottom Layer w0.5: R50_Low.1@49.706,62.3 50.121,62.715 50.121,63.521 50.8,64.2 59,64.2 59.62,63.58 60.98,63.58 C34_Low.1@61,63.6 ; C34_Low.1@61.18,63.68 C34_Low.1@61.1,63.6 61.18,63.52 61.18,62.82 v1(61.2,62.8)
  Bottom Layer w0.7: v1(38.3,60.7) 43.145,60.7 44.546,62.101 49.391,62.101 49.59,62.3 R50_Low.1@49.706,62.3
Cell10_High: J1_High.10 R27_High.1 R28_High.1 | length 19.9
  Top Layer w0.3: R28_High.1@149.279,41.571 149.279,41.621 152.579,44.921 R27_High.1@152.579,46.771 153.979,46.771 155.779,48.571 J1_High.10@165.167,48.571
Cell10_Low: J1_Low.10 R27_Low.1 R28_Low.1 | length 19.9
  Top Layer w0.3: J1_Low.10@43.612,62 53,62 54.8,63.8 R27_Low.1@56.2,63.8 56.2,65.65 59.5,68.95 R28_Low.1@59.5,69
Cell10_S_High: BMS_IC1_High.20 C35_High.1 D10_High.2 J1_High.9 R51_High.1 | length 78.4
  Top Layer w0.3: BMS_IC1_High.20@143.05,43.962 143.462,43.962 v1(143.5,44)
  Top Layer w0.6: D10_High.2@143.6,76.9 v1(143.6,77.8)
  Top Layer w0.7: J1_High.9@168.494,48.586 168.509,48.601 v1(170.479,48.601)
  Layer 2 w0.3: v1(143.6,77.8) 146.2,75.2 146.2,72 151.669,66.531 151.669,49.594 145.446,43.371 144.179,43.371 v1@143.673,43.877
  Bottom Layer w0.3: C35_High.1@143.499,43.352 C35_High.1@143.679,43.171 143.529,43.321 143.529,43.971 v1(143.5,44)
  Bottom Layer w0.5: v1(143.5,44) 144.371,44.871 146.179,44.871 148.779,42.271 157.979,42.271 158.658,42.95 158.658,43.756 R51_High.1@159.073,44.171
  Bottom Layer w0.7: R51_High.1@159.073,44.171 162.718,44.171 167.148,48.601 v1(170.479,48.601)
Cell10_S_Low: BMS_IC1_Low.20 C35_Low.1 D10_Low.2 J1_Low.9 R51_Low.1 | length 78.9
  Top Layer w0.3: v1(65.279,66.571) 65.317,66.609 BMS_IC1_Low.20@65.729,66.609
  Top Layer w0.6: v1(65.2,32.2) D10_Low.2@65.2,33.1
  Top Layer w0.7: v1(38.3,61.97) 40.27,61.97 J1_Low.9@40.285,61.985
  Layer 2 w0.3: v1@65.106,66.694 64.6,67.2 63.332,67.2 57.11,60.977 57.11,43.49 62.6,38 62.6,34.8 v1(65.2,32.2)
  Bottom Layer w0.3: v1(65.279,66.571) 65.25,66.6 65.25,67.25 C35_Low.1@65.1,67.4 C35_Low.1@65.28,67.22
  Bottom Layer w0.5: R51_Low.1@49.706,66.4 50.121,66.815 50.121,67.621 50.8,68.3 60,68.3 62.6,65.7 64.407,65.7 v1(65.279,66.571)
  Bottom Layer w0.7: v1(38.3,61.97) 41.63,61.97 46.061,66.4 R51_Low.1@49.706,66.4
Cell11_High: J1_High.8 R29_High.1 | length 26.7
  Top Layer w0.3: R29_High.1@142.979,36.471 146.179,36.471 157.079,47.371 J1_High.8@165.203,47.371
Cell11_Low: J1_Low.8 R29_Low.1 | length 26.7
  Top Layer w0.3: J1_Low.8@43.575,63.2 51.7,63.2 62.6,74.1 R29_Low.1@65.8,74.1
Cell11_S_High: BMS_IC1_High.17 C36_High.1 D11_High.2 J1_High.7 R52_High.1 | length 84.5
  Top Layer w0.3: BMS_IC1_High.17@141.55,43.962 141.55,42.912 141.546,42.908 141.546,42.492 141.976,42.062 141.976,41.526 v1(142.004,41.497)
  Top Layer w0.6: D11_High.2@145.3,77 v1(145.3,77.8)
  Top Layer w0.7: J1_High.7@168.494,47.316 168.509,47.331 v1(170.479,47.331)
  Layer 2 w0.3: v1(142.004,41.497) 144.768,41.497 152.472,49.201 152.472,67.428 147.7,72.2 147.7,75.4 v1(145.3,77.8)
  Bottom Layer w0.5: v1(142.004,41.497) 145.33,38.171 157.968,38.171 158.658,38.861 158.658,38.961 158.973,39.276 R52_High.1@159.073,39.276
  Bottom Layer w0.7: R52_High.1@159.073,40.071 159.073,40.766 159.388,41.081 161.808,41.081 168.058,47.331 v1(170.479,47.331)
Cell11_S_Low: BMS_IC1_Low.17 C36_Low.1 D11_Low.2 J1_Low.7 R52_Low.1 | length 85.2
  Top Layer w0.3: v1(66.774,69.074) 67.233,68.616 67.233,67.663 67.229,67.659 BMS_IC1_Low.17@67.229,66.609
  Top Layer w0.6: v1(63.5,32.2) D11_Low.2@63.5,33
  Top Layer w0.7: v1(38.3,63.24) 40.27,63.24 J1_Low.7@40.285,63.255
  Layer 2 w0.3: v1(63.5,32.2) 61.1,34.6 61.1,37.7 56.306,42.494 56.306,61.371 64.01,69.074 v1(66.774,69.074)
  Bottom Layer w0.5: R52_Low.1@49.706,71.295 49.806,71.295 50.121,71.61 50.121,71.71 50.811,72.4 63.65,72.4 65.5,70.55 C36_Low.1@65.5,70.5 65.5,70.45 66.774,69.176 v1(66.774,69.074)
  Bottom Layer w0.7: v1(38.3,63.24) 40.721,63.24 46.97,69.49 49.391,69.49 49.706,69.805 R52_Low.1@49.706,70.5
Cell12_High: J1_High.6 R30_High.1 R31_High.1 | length 29.6
  Top Layer w0.3: R31_High.1@140.559,36.291 R31_High.1@140.379,36.471 R30_High.1@141.679,36.471 R30_High.1@141.728,36.471 ; R30_High.1@141.728,36.271 142.328,35.671 147.579,35.671 157.979,46.071 J1_High.6@165.152,46.071
Cell12_Low: J1_Low.6 R30_Low.1 R31_Low.1 | length 29.6
  Top Layer w0.3: J1_Low.6@43.627,64.5 50.8,64.5 61.2,74.9 66.45,74.9 R30_Low.1@67.05,74.3 ; R30_Low.1@67.05,74.1 R30_Low.1@67.1,74.1 R31_Low.1@68.4,74.1 R31_Low.1@68.22,74.28
Cell12_S_High: BMS_IC1_High.13 C37_High.1 D12_High.2 J1_High.5 R53_High.1 | length 94.2
  Top Layer w0.3: BMS_IC1_High.13@139.55,43.962 139.55,42.775 139.546,42.771 139.546,42.105 139.722,41.93 139.963,41.93 140.23,41.663 v1(140.27,41.663)
  Top Layer w0.6: D12_High.2@147,76.9 v1(147,77.8)
  Top Layer w0.7: J1_High.5@168.494,46.046 168.509,46.061 v1(170.479,46.061)
  Layer 2 w0.3: v1(140.27,41.663) 140.27,41.521 140.577,41.214 141.42,40.371 144.779,40.371 153.275,48.868 153.275,68.425 149.3,72.4 149.3,75.5 v1(147,77.8)
  Bottom Layer w0.5: v1(140.27,41.663) 140.27,40.63 140.699,40.201 140.699,40.152 140.859,39.991 140.859,39.775 146.562,34.071 157.779,34.071 158.569,34.861 158.658,34.861 159.073,35.276 R53_High.1@159.073,35.971
  Bottom Layer w0.7: R53_High.1@159.073,35.971 159.073,36.666 168.468,46.061 v1(170.479,46.061)
Cell12_S_Low: BMS_IC1_Low.13 C37_Low.1 D12_Low.2 J1_Low.5 R53_Low.1 | length 94.8
  Top Layer w0.3: v1(68.731,68.88) 69.233,68.378 69.233,67.801 69.229,67.797 BMS_IC1_Low.13@69.229,66.609
  Top Layer w0.6: v1(61.8,32.2) D12_Low.2@61.8,33.1
  Top Layer w0.7: v1(38.3,64.51) 40.27,64.51 J1_Low.5@40.285,64.525
  Layer 2 w0.3: v1(61.8,32.2) 59.5,34.5 59.5,37.7 55.503,41.697 55.503,61.703 64,70.2 67.359,70.2 68.122,69.437 68.173,69.437 v1(68.731,68.88)
  Bottom Layer w0.5: R53_Low.1@49.706,74.6 49.706,75.295 50.121,75.71 50.21,75.71 51,76.5 62.216,76.5 67.92,70.796 67.92,70.58 68.08,70.42 68.08,70.37 68.731,69.719 v1(68.731,68.88)
  Bottom Layer w0.7: v1(38.3,64.51) 40.311,64.51 49.706,73.905 R53_Low.1@49.706,74.6
Cell13_High: J1_High.4 R32_High.1 | length 30.6
  Top Layer w0.3: R32_High.1@139.079,36.471 R32_High.1@139.129,36.471 ; R32_High.1@139.129,36.271 140.429,34.971 148.579,34.971 158.379,44.771 J1_High.4@165.041,44.771
Cell13_Low: J1_Low.4 R32_Low.1 | length 30.6
  Top Layer w0.3: J1_Low.4@43.738,65.8 50.4,65.8 60.2,75.6 68.35,75.6 R32_Low.1@69.65,74.3 ; R32_Low.1@69.65,74.1 R32_Low.1@69.7,74.1
Cell13_S_High: BMS_IC1_High.10 C38_High.1 D13_High.2 J1_High.3 R54_High.1 | length 103.7
  Top Layer w0.3: BMS_IC1_High.10@138.05,43.962 138.05,42.887 138.046,42.883 138.046,41.704 v1(138.379,41.371)
  Top Layer w0.6: D13_High.2@148.7,77 v1(148.7,77.8)
  Top Layer w0.7: J1_High.3@168.494,44.776 169.599,44.776 169.604,44.771 v1(170.479,44.771)
  Layer 2 w0.3: v1(138.379,41.371) 140.28,39.47 145.177,39.47 154.079,48.371 154.079,69.421 150.8,72.7 150.8,75.7 v1(148.7,77.8)
  Bottom Layer w0.5: C38_High.1@138.279,40.022 C38_High.1@138.279,40.071 ; v1(138.379,41.371) 138.279,41.271 C38_High.1@138.279,40.071 ; R54_High.1@140.079,33.077 139.664,33.492 138.958,33.492 138.179,34.271 138.179,39.471 138.199,39.491 138.199,39.991 C38_High.1@138.279,40.071
  Bottom Layer w0.7: R54_High.1@140.079,33.077 140.385,32.771 160.079,32.771 168.379,41.071 168.379,43.171 169.979,44.771 v1(170.479,44.771)
Cell13_S_Low: BMS_IC1_Low.10 C38_Low.1 D13_Low.2 J1_Low.3 R54_Low.1 | length 104.2
  Top Layer w0.3: v1(70.4,69.2) 70.733,68.867 70.733,67.688 70.729,67.684 BMS_IC1_Low.10@70.729,66.609
  Top Layer w0.6: v1(60.1,32.2) D13_Low.2@60.1,33
  Top Layer w0.7: v1(38.3,65.8) 39.175,65.8 39.18,65.795 J1_Low.3@40.285,65.795
  Layer 2 w0.3: v1(60.1,32.2) 54.7,37.6 54.7,62.2 63.602,71.102 68.498,71.102 v1(70.4,69.2)
  Bottom Layer w0.5: R54_Low.1@68.7,77.494 69.115,77.079 69.821,77.079 70.6,76.3 70.6,71.1 70.58,71.08 70.58,70.58 C38_Low.1@70.5,70.5 70.5,69.3 v1(70.4,69.2)
  Bottom Layer w0.7: v1(38.3,65.8) 38.8,65.8 40.4,67.4 40.4,69.5 48.7,77.8 68.394,77.8 R54_Low.1@68.7,77.494
Cell14_High: J1_High.2 R33_High.1 | length 32
  Top Layer w0.3: R33_High.1@137.779,36.471 137.828,36.471 139.928,34.371 140.029,34.271 150.579,34.271 159.779,43.471 J1_High.2@165.08,43.471
Cell14_Low: J1_Low.2 R33_Low.1 | length 32
  Top Layer w0.3: J1_Low.2@43.698,67.1 49,67.1 58.2,76.3 68.75,76.3 68.85,76.2 70.95,74.1 R33_Low.1@71,74.1
Cell14_S_High: D14_High.2 J1_High.1 R55_High.1 R63_High.1 R65_High.1 R66_High.1 | length 152.9
  Top Layer w0.3: R66_High.1@133.579,39.671 133.628,39.671 133.809,39.491 133.809,39.441 134.179,39.071 ; R65_High.1@134.879,39.671 134.829,39.671 134.204,39.046 134.179,39.071 ; v1(150.4,77.8) 161.75,77.8 168.379,71.171 171.179,71.171 172.879,69.471 172.879,45.901 v1@170.464,43.486 ; J1_High.1@168.494,43.506 168.429,43.441 168.429,41.521 166.979,40.071 158.279,40.071 151.779,33.571 137.379,33.571 134.179,36.771 134.179,39.071
  Top Layer w0.6: D14_High.2@150.4,76.9 v1(150.4,77.8)
  Top Layer w0.7: J1_High.1@168.494,43.506 J1_High.1@169.279,43.506 ; J1_High.1@169.279,43.501 169.294,43.486 v1@170.464,43.486
  Top Layer w0.75: R63_High.1@162.762,37.1 165.282,37.1 169.279,41.096 169.279,43.501 J1_High.1@169.279,43.506
  Bottom Layer w0.7: R55_High.1@135.979,33.077 136.674,33.077 R55_High.1@136.989,32.762 ; R55_High.1@136.989,32.761 138.079,31.671 161.179,31.671 170.479,40.971 170.479,43.471 v1@170.464,43.486
  other v1: 170.479,43.486
Cell14_S_Low: D14_Low.2 J1_Low.1 R55_Low.1 R63_Low.1 R65_Low.1 R66_Low.1 | length 153.1
  Top Layer w0.3: v1@38.315,67.085 35.9,64.67 35.9,41.1 37.6,39.4 40.4,39.4 47.6,32.2 v1(58.4,32.2) ; J1_Low.1@40.285,67.065 40.35,67.13 40.35,69.05 41.8,70.5 50.5,70.5 57,77 71.4,77 74.6,73.8 74.6,71.5 ; R65_Low.1@73.9,70.9 73.95,70.9 74.575,71.525 74.6,71.5 ; R66_Low.1@75.2,70.9 75.15,70.9 74.97,71.08 74.97,71.13 74.6,71.5
  Top Layer w0.6: v1(58.4,32.2) D14_Low.2@58.4,33.1
  Top Layer w0.7: v1@38.315,67.085 39.485,67.085 J1_Low.1@39.5,67.07 ; J1_Low.1@39.5,67.065 J1_Low.1@40.285,67.065
  Top Layer w0.75: J1_Low.1@39.5,67.065 39.5,67.07 39.5,69.475 43.525,73.5 R63_Low.1@46.002,73.5
  Bottom Layer w0.7: v1@38.315,67.085 38.3,67.1 38.3,69.6 47.6,78.9 70.7,78.9 R55_Low.1@71.79,77.81 ; R55_Low.1@71.79,77.809 72.105,77.494 R55_Low.1@72.8,77.494
  other v1: 38.3,67.085
Cell_Depopulation_High: BMS_IC1_High.2 BMS_IC1_High.3 BMS_IC1_High.4 BMS_IC1_High.5 BMS_IC1_High.6 BMS_IC1_High.7 BMS_IC1_High.8 C44_High.2 R65_High.2 | length 6.1
  Top Layer w0.3: BMS_IC1_High.2@134.05,43.962 BMS_IC1_High.3@134.55,43.962 BMS_IC1_High.4@135.05,43.962 ; R65_High.2@134.879,41.071 134.979,41.171 C44_High.2@134.979,42.371 C44_High.2@134.907,42.3 ; C44_High.2@134.879,42.371 135.05,42.543 BMS_IC1_High.4@135.05,43.962 ; BMS_IC1_High.8@137.05,43.962 BMS_IC1_High.7@136.55,43.962 BMS_IC1_High.6@136.05,43.962 BMS_IC1_High.5@135.55,43.962 BMS_IC1_High.4@135.05,43.962
Cell_Depopulation_Low: BMS_IC1_Low.2 BMS_IC1_Low.3 BMS_IC1_Low.4 BMS_IC1_Low.5 BMS_IC1_Low.6 BMS_IC1_Low.7 BMS_IC1_Low.8 C44_Low.2 R65_Low.2 | length 6.1
  Top Layer w0.3: BMS_IC1_Low.8@71.729,66.609 BMS_IC1_Low.7@72.229,66.609 BMS_IC1_Low.6@72.729,66.609 BMS_IC1_Low.5@73.229,66.609 BMS_IC1_Low.4@73.729,66.609 ; C44_Low.2@73.871,68.271 C44_Low.2@73.8,68.2 73.8,69.4 R65_Low.2@73.9,69.5 ; C44_Low.2@73.9,68.2 73.729,68.029 BMS_IC1_Low.4@73.729,66.609 ; BMS_IC1_Low.2@74.729,66.609 BMS_IC1_Low.3@74.229,66.609 BMS_IC1_Low.4@73.729,66.609
Collector_High: C43_High.1 D15_High.2 Q1_High.2 | length 34.2
  Top Layer w1: Q1_High.2@124.479,36.146 124.854,35.771 129.579,35.771 129.7,35.65 132.979,32.371 156.579,32.371 156.854,32.646 D15_High.2@156.854,32.771
Collector_Low: C43_Low.1 D15_Low.2 Q1_Low.2 | length 34.2
  Top Layer w1: D15_Low.2@51.925,77.8 51.925,77.925 52.2,78.2 75.8,78.2 C43_Low.1@79.2,74.8 83.925,74.8 Q1_Low.2@84.3,74.425
Drive_High: BMS_IC1_High.65 C39_High.2 R64.1@129.6,43.2 | length 16.1
  Top Layer w0.3: C39_High.2@128.3,53.3 128.4,53.4 v1(130.241,53.4) 130.291,53.45 BMS_IC1_High.65@131.562,53.45
  Top Layer w0.6: R64.1@129.6,43.2 v1(129.6,44)
  Bottom Layer w0.6: v1(129.6,44) 128.7,44 127.5,45.2 127.5,50.659 v1(130.241,53.4)
Drive_Low: BMS_IC1_Low.65 C39_Low.2 R64.1@79.4,67.3 | length 16.5
  Top Layer w0.3: BMS_IC1_Low.65@77.217,57.121 78.488,57.121 v1(78.538,57.171) C39_Low.2@80.271,57.171 ; C39_Low.2@80.22,57.1 C39_Low.2@80.4,57.28 ; C39_Low.2@80.271,57.171 ccw(c80.271,57.3) C39_Low.2@80.4,57.3 cw(c80.271,57.3) 80.398,57.278 cw(c80.271,57.3) 80.293,57.173 cw(c80.271,57.3) C39_Low.2@80.271,57.171
  Top Layer w0.6: v1(79.4,66.5) R64.1@79.4,67.3
  Bottom Layer w0.6: v1(78.538,57.171) 78.871,57.171 81.3,59.6 81.3,65.4 80.2,66.5 v1(79.4,66.5)
Emitter_High: L1_High.1 Q1_High.3 | length 3.3
  Top Layer w0.6: Q1_High.3@122.194,42.671 122.129,42.736 122.129,44.696 L1_High.1@123.004,45.571
Emitter_Low: L1_Low.1 Q1_Low.3 | length 3.3
  Top Layer w0.6: L1_Low.1@85.775,65 86.65,65.875 86.65,67.835 Q1_Low.3@86.585,67.9
GND_High: BMS_IC1_High.61 BMS_IC1_High.64 BMS_IC1_High.67 BMS_IC1_High.81 C1_High.2 C2_High.2 C3_High.2 C4_High.2 C5_High.2 C6_High.2 C7_High.2 C8_High.2 C9_High.2 C10_High.2 C39_High.1 C40_High.1 C41_High.1 C42_High.1 C43_High.2 C44_High.1 C45_High.2 C56.2 C57.2 C58.1 C59.2 C61.2 C63.1 D18.2 D19.1 J1_High.29 R34_High.2 | length 13.1
  Top Layer w0.3: v1(130.4,52.6) 130.441,52.6 130.591,52.45 BMS_IC1_High.67@131.562,52.45 132.305,52.45 132.551,52.696 132.551,53.704 ; BMS_IC1_High.64@131.562,53.95 132.305,53.95 132.551,53.704 ; BMS_IC1_High.61@131.562,55.45 132.305,55.45 132.551,55.204 132.551,53.704
  Top Layer w0.5: v1(136.179,41.671) 136.179,41.948 136.298,42.068 136.298,42.291 C44_High.1@136.379,42.371
  Top Layer w0.6: C43_High.2@129.579,37.171 v1(129.579,37.771) ; v1(132.179,41.471) C45_High.2@132.179,42.271
  Top Layer w0.7: J1_High.29@168.494,61.286 168.509,61.301 v1(170.479,61.301)
  Bottom Layer w0.7: v1(170.479,61.301) 170.801,61.301 171.67,62.17 171.67,62.48 171.68,62.48 R34_High.2@171.7,62.5
  other v2: 111.7,35.2 111.7,36.2 111.7,37.3 111.7,38.4 111.7,39.4 111.7,40.5 111.7,41.5 111.7,42.6 111.7,43.6 111.7,44.7 111.7,45.8 134.629,46.829 136.629,46.829 138.629,46.829 140.629,46.829 142.629,46.829 111.7,46.9 125.9,48.05 134.629,48.829 136.629,48.829 138.629,48.829 140.629,48.829 142.629,48.829 125.9,49.95 134.629,50.829 136.629,50.829 138.629,50.829 140.629,50.829 142.629,50.829 125.9,51.223 134.629,52.829 136.629,52.829 138.629,52.829 140.629,52.829 142.629,52.829 125.9,53.25 134.629,54.829 136.629,54.829 138.629,54.829 140.629,54.829 142.629,54.829 128.1,57.2 119.2,57.5 120.5,57.8 119.2,58.8 126.9,58.9 127.9,58.9 121.5,59 120.5,60 125.65,66.5 127.4,67.1 125.95,67.2 125.65,67.9
  other v3: 129.5,39.5
GND_Low: BMS_IC1_Low.61 BMS_IC1_Low.64 BMS_IC1_Low.67 BMS_IC1_Low.81 C1_Low.2 C2_Low.2 C3_Low.2 C4_Low.2 C5_Low.2 C6_Low.2 C7_Low.2 C8_Low.2 C9_Low.2 C10_Low.2 C39_Low.1 C40_Low.1 C41_Low.1 C42_Low.1 C43_Low.2 C44_Low.1 C45_Low.2 C46.2 C48.2 C50.1 C51.1 C52.2 C53.1 D16.1 D17.2 J1_Low.29 R34_Low.2 | length 12.5
  Top Layer w0.3: BMS_IC1_Low.61@77.217,55.121 76.473,55.121 76.228,55.367 76.228,56.867 ; BMS_IC1_Low.64@77.217,56.621 76.473,56.621 76.228,56.867 ; v1(78.379,57.971) 78.338,57.971 78.188,58.121 BMS_IC1_Low.67@77.217,58.121 76.473,58.121 76.228,57.876 76.228,56.867
  Top Layer w0.5: C44_Low.1@72.4,68.2 v1(72.4,68.9)
  Top Layer w0.6: C45_Low.2@76.6,68.3 v1(76.6,69) ; v1(79.2,72.8) C43_Low.2@79.2,73.4
  Top Layer w0.7: v1(38.3,49.27) 40.27,49.27 J1_Low.29@40.285,49.285
  Bottom Layer w0.7: R34_Low.2@37.1,48.6 37.12,48.62 37.13,48.62 37.15,48.64 37.15,48.65 37.77,49.27 v1(38.3,49.27)
  other v2: 86,44.5 86.8,45.5 87.6,45.525 86,46.5 78.3,49.6 79.677,50.077 78.3,50.6 87,55 85.6,55.7 86.7,55.7 66,56 68,56 70,56 72,56 74,56 87,56.4 82.8,57.3 66,58 68,58 70,58 72,58 74,58 82.8,58.9 66,60 68,60 70,60 72,60 74,60 82.8,60.6 97.041,61.559 66,62 68,62 70,62 72,62 74,62 82.8,62.5 97,62.8 97,63.9 66,64 68,64 70,64 72,64 74,64 97,65 97,66 97,67.1 97,68.1 97,69.2 97,70.2 97,71.3 97,72.4 97,73.4
  other v3: 79.4,71.1
IA_High_Intr_N: C54.1 R77.2 | length 16.2
  Top Layer w0.6: C54.1@105.475,63.8 105.652,63.977 105.652,65.247 106.003,65.598 v1@107.589,65.598 ; v1(109,66.7) 109.082,66.618 113.877,66.618 114.76,67.501 118.451,67.501 118.7,67.75 R77.2@118.7,67.8
  Layer 1 w0.6: v1(107.6,65.587) 107.6,66.191 108.26,66.851 108.849,66.851 v1(109,66.7)
IA_High_Intr_P: C55.1 R78.2 | length 15.4
  Top Layer w0.6: C55.1@105.475,67.6 105.475,66.674 105.652,66.498 107.841,66.498 108.189,66.15 v1(108.55,66.15) ; v1(109.4,65.8) 109.516,65.916 114.167,65.916 115.05,66.799 R78.2@118.451,66.799 ; R78.2@118.7,66.5 R78.2@118.7,66.55 ; R78.2@118.451,66.799 R78.2@118.613,66.637 ; R78.2@118.451,66.799 R78.2@118.613,66.637 ; R78.2@118.613,66.637 R78.2@118.7,66.55 ; R78.2@118.613,66.637 R78.2@118.7,66.55
  Layer 1 w0.6: v1(108.55,66.15) 108.9,65.8 v1(109.4,65.8)
IA_High_N: BMS_IC1_High.58 C57.1 R77.1 R79.1 | length 22.3
  Top Layer w0.3: R77.1@120.1,67.8 120.1,67.78 120.28,67.6 121.15,67.6 R79.1@122.65,69.1 ; R79.1@122.7,69.1 R79.1@122.65,69.1 ; C57.1@126.7,69.1 R79.1@122.65,69.1 ; C57.1@126.75,69.1 129.642,66.207 129.642,64.126 134.501,59.267 134.501,58.44 134.55,58.391 BMS_IC1_High.58@134.55,57.438
IA_High_P: BMS_IC1_High.59 C58.2 R78.1 R80.1 | length 21.4
  Top Layer w0.3: R78.1@120.1,66.5 120.1,66.519 120.28,66.699 121.151,66.699 122.47,65.38 122.52,65.38 R80.1@122.7,65.2 C58.2@126.7,65.2 ; C58.2@126.75,65.2 128.292,66.742 128.54,66.742 129.241,66.041 129.241,63.959 134.099,59.101 134.099,58.44 134.05,58.391 BMS_IC1_High.59@134.05,57.438
IA_Low_CMC_N: D17.1 L2.3 R71.2 R72.1 | length 8.4
  Top Layer w0.3: R72.1@85.9,42.3 87.55,42.3 D17.1@87.6,42.35 87.6,43.337 89.7,45.438 89.7,45.65 90,45.95 L2.3@90.225,45.95 90.525,45.65 90.8,45.65 R71.2@91.62,44.83
IA_Low_CMC_P: D16.2 L2.2 R67.1 R69.2 | length 6.6
  Top Layer w0.3: R67.1@85.9,48.7 87.55,48.7 D16.2@87.6,48.65 90.025,48.65 L2.2@90.225,48.45 90.45,48.45 R69.2@91.8,49.8
IA_Low_Iso_N: C49.1 L2.4 R71.1 | length 10
  Top Layer w0.3: R71.1@93.3,44.75 93.38,44.83 94.2,45.65 94.475,45.65 L2.4@94.775,45.95 94.893,46.068 94.893,46.823 95.068,46.999 96.001,46.999 97.999,45.001 97.999,44.752 97.823,44.577 96.627,44.577 C49.1@96.3,44.25 ; C49.1@95.274,44.25 C49.1@96.2,44.25
IA_Low_Iso_P: C47.1 L2.1 R69.1 | length 11.1
  Top Layer w0.3: R69.1@93.2,49.8 93.2,49.75 94.2,48.75 94.475,48.75 L2.1@94.775,48.45 ; L2.1@94.893,48.332 94.893,47.577 95.068,47.401 96.167,47.401 98.401,45.167 98.401,44.752 98.577,44.577 99.773,44.577 C47.1@100.1,44.25 99.175,44.25 C47.1@98.848,44.577
IA_Low_N: BMS_IC1_Low.58 C50.2 R70.1 R72.2 | length 18.7
  Top Layer w0.3: BMS_IC1_Low.58@74.229,53.133 74.229,52.546 74.278,52.497 74.278,51.829 74.997,51.111 76.294,51.111 76.968,50.436 76.968,49.282 77.55,48.7 C50.2@77.6,48.7 77.771,48.871 78.43,48.871 79.109,49.55 79.718,49.55 80.908,48.361 81.8,47.469 81.8,44.45 83.25,43 R70.1@83.3,43 83.48,42.82 84.03,42.82 84.5,42.35 R72.2@84.5,42.3
IA_Low_P: BMS_IC1_Low.59 C46.1 R67.2 R68.2 | length 14.1
  Top Layer w0.3: BMS_IC1_Low.59@74.729,53.133 74.729,52.546 74.68,52.497 74.68,51.996 75.163,51.512 76.46,51.512 77.103,50.869 77.519,50.869 78.07,51.42 78.72,51.42 C46.1@78.9,51.6 78.95,51.6 80.204,50.345 80.204,49.632 81.982,47.854 83.07,47.854 83.216,48 R68.2@83.3,48 83.48,48.18 84.03,48.18 84.5,48.65 R67.2@84.5,48.7
IA_Out_N: C49.2 J2.1 | length 4.5
  Top Layer w0.3: C49.2@96.3,40.9 96.627,40.573 97.823,40.573 97.999,40.398 97.999,39.421 97.999,38.901 97.823,38.725 97.725,38.725 J2.1@97.2,38.2
IA_Out_P: C47.2 J2.3 | length 4.6
  Top Layer w0.3: J2.3@99.2,38.2 98.944,38.2 98.401,38.743 98.401,39.588 98.401,40.398 98.577,40.573 99.773,40.573 C47.2@100.1,40.9
IB_High_CMC_N: D18.1 L3.3 R81.1 R83.2 | length 10.2
  Top Layer w0.3: R83.2@114.1,60 114.1,59.95 115.1,58.95 115.475,58.95 L3.3@115.775,58.65 116,58.65 117.413,60.063 117.9,60.063 118,60.162 D18.1@118,60.45 118,60.737 118.363,61.1 122.25,61.1 122.3,61.05 R81.1@122.3,61.1
IB_High_CMC_P: D19.2 L3.2 R84.2 R86.1 | length 9.2
  Top Layer w0.3: R84.2@114.1,54.8 114.1,54.85 115.1,55.85 115.475,55.85 115.925,56.3 120.4,56.3 120.5,56.4 D19.2@120.5,56.55 120.55,56.6 122.134,56.6 R86.1@122.3,56.766 ; R86.1@122.3,56.55 R86.1@122.3,56.6
IB_High_Iso_N: C60.1 L3.4 R83.1 | length 9.9
  Top Layer w0.3: L3.4@111.45,58.65 111.75,58.95 111.75,59 112.7,59.95 R83.1@112.7,60
  Top Layer w0.6: C60.1@105.6,54.475 105.777,54.652 106.748,54.652 107.099,55.003 107.099,55.792 109.058,57.751 110.499,57.751 110.85,58.102 110.85,58.5 111,58.65 L3.4@111.225,58.65
IB_High_Iso_P: C62.1 L3.1 R84.1 | length 8.8
  Top Layer w0.3: L3.1@111.45,56.15 111.75,55.85 111.75,55.8 112.7,54.85 R84.1@112.7,54.8
  Top Layer w0.6: C62.1@109.3,54.475 109.123,54.652 108.152,54.652 107.801,55.003 107.801,55.502 109.348,57.049 110.499,57.049 110.85,56.698 110.85,56.3 111,56.15 L3.1@111.225,56.15
IB_High_N: BMS_IC1_High.62 C59.1 R81.2 R82.2 | length 12.5
  Top Layer w0.3: R81.2@123.7,61.1 123.85,60.95 124.75,60.95 R82.2@124.9,60.8 127.15,60.8 129.9,58.05 129.9,57.95 129.321,57.371 129.321,56.511 129.688,56.144 129.688,55.581 130.368,54.901 130.925,54.901 130.974,54.95 BMS_IC1_High.62@131.562,54.95
IB_High_P: BMS_IC1_High.63 C63.2 R85.1 R86.2 | length 9.4
  Top Layer w0.3: R86.2@123.7,56.65 R86.2@123.7,56.6 123.85,56.75 124.75,56.75 R85.1@124.9,56.9 125,56.8 127.2,56.8 127.48,56.52 127.659,56.52 127.706,56.473 128.791,56.473 129.286,55.978 129.286,55.415 130.202,54.499 130.925,54.499 130.974,54.45 BMS_IC1_High.63@131.562,54.45
IB_Low_Intr_N: C54.2 R75.1 | length 18.7
  Top Layer w0.6: R75.1@92.679,53.771 92.679,54.969 93.03,55.32 95.413,55.32 100.3,60.208 100.3,64.551 101.098,65.349 101.597,65.349 101.948,64.998 101.948,63.977 C54.2@102.125,63.8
